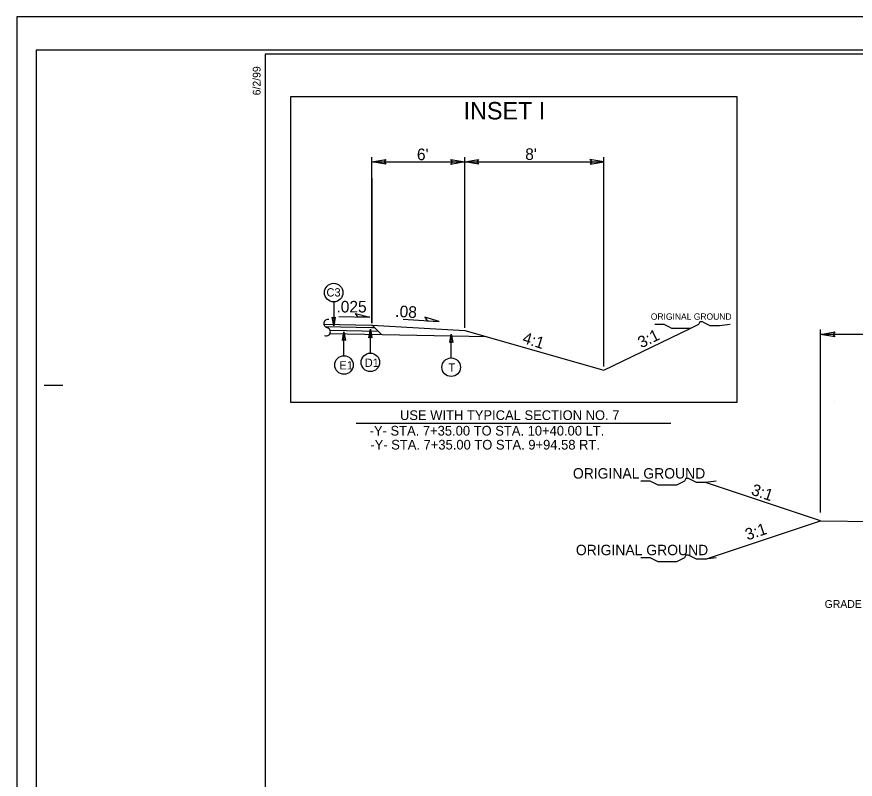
# Model space of a CAD drawing. Extents: x 958711 to 962106, y 831169 to 840840.
# Drawn here: x 958711 to 959274, y 836655 to 837167 of the extents above; entities that cross this region are included whole.
import ezdxf

# ---------------------------------------------------------------- set-up
doc = ezdxf.new("R2010")
doc.units = 0
for name, color, linetype in [('Old_Level_1', 7, 'Continuous'), ('Old_Level_11', 7, 'Continuous'), ('Old_Level_21', 7, 'Continuous'), ('Old_Level_3', 7, 'Continuous'), ('Prop Dimension Text', 7, 'Continuous'), ('Sheet Plot Border Inside CELL', 7, 'Continuous'), ('Sheet Plot Border Outside CELL', 7, 'Continuous'), ('Sheet Typical CELL', 7, 'Continuous'), ('Typical ID Circle CELL', 7, 'Continuous'), ('Typical Terminator CELL', 7, 'Continuous'), ('Typical Text ID Circle CELL', 7, 'Continuous')]:
    doc.layers.add(name, color=color, linetype=linetype)

msp = doc.modelspace()

# ---------------------------------------------------------------- linework, layer by layer
at = {"layer": 'Old_Level_1'}
for p, q in [((958949.49, 836961.06), (958949.49, 837072.49)), ((958949.49, 837069.23), (959011.81, 837069.23)), ((959011.81, 836957.83), (959011.81, 837072.49)), ((959011.81, 837069.23), (959105.29, 837069.23)), ((959105.29, 836931.97), (959105.29, 837072.49)), ((958949.49, 837058.45), (958949.49, 836961)), ((958927.19, 836965.53), (958948.07, 836965.11)), ((958970.53, 836963.64), (958994.65, 836962.16)), ((958917.11, 836960.39), (958949.49, 836959.73)), ((958917.99, 836958.64), (958949.49, 836958.01)), ((958921.3, 836956.32), (958953.71, 836955.66)), ((958949.49, 836959.73), (958949.64, 836959.73)), ((958949.49, 836958.01), (958951.41, 836957.97)), ((958949.64, 836959.73), (958956.01, 836953.36)), ((959105.29, 836929.34), (959163.42, 836957.5)), ((959250.92, 836833.83), (959250.92, 836956.73)), ((958921.29, 836954.06), (959026.37, 836951.94)), ((959317.47, 836953.48), (959250.92, 836953.48)), ((958938.84, 836893.76), (959150.25, 836893.76)), ((959250.92, 836828.25), (959173.74, 836853.98)), ((959173.74, 836802.52), (959250.92, 836828.25)), ((959250.92, 836828.25), (959313.91, 836827.62))]:
    msp.add_line(p, q, dxfattribs=at)
msp.add_lwpolyline([(958894.91, 837113.12), (959194.72, 837113.12), (959194.72, 836907.71), (958894.91, 836907.71)], close=True, dxfattribs=at)
for points in [[(958949.65, 836959.72), (959011.81, 836956.11)], [(959011.81, 836956.11), (959105.29, 836929.34)]]:
    msp.add_lwpolyline(points, dxfattribs=at)
for centre, start, end in [((958919.91, 836960.7), 79.4545, 256.8065), ((958918.72, 836955.2), 248.3355, 78.8593)]:
    msp.add_arc(centre, 2.81, start, end, dxfattribs=at)
at = {"layer": 'Old_Level_11'}
for p, q in [((958940.07, 836965.27), (958938.34, 836967.53)), ((958938.34, 836967.53), (958948.07, 836965.11)), ((958948.07, 836965.11), (958940.07, 836965.27)), ((958985, 836964.98), (958986.65, 836962.65)), ((958994.65, 836962.16), (958985, 836964.98)), ((958986.65, 836962.65), (958994.65, 836962.16))]:
    msp.add_line(p, q, dxfattribs=at)
for points in [[(959260.53, 836951.82), (959250.92, 836953.48), (959260.58, 836955.19), (959259.36, 836953.48)], [(959260.64, 836908.05), (959260.51, 836908.07), (959260.64, 836908.1), (959260.63, 836908.07)]]:
    msp.add_lwpolyline(points, close=True, dxfattribs=at)
at = {"layer": 'Old_Level_21'}
for points in [[(959190.14, 836960.15), (959183.04, 836959.27), (959181.26, 836959.27), (959178.61, 836959.27), (959176.83, 836959.27), (959175.06, 836960.15), (959173.28, 836961.04), (959171.51, 836961.92), (959169.74, 836961.92), (959168.84, 836960.15), (959167.08, 836959.27), (959165.3, 836958.37), (959163.53, 836957.5), (959161.75, 836957.5), (959159.98, 836957.5), (959158.21, 836957.5), (959156.44, 836957.5), (959154.66, 836957.5), (959152.89, 836957.5), (959151.11, 836957.5), (959149.34, 836958.37), (959147.57, 836959.27), (959145.8, 836960.15), (959143.13, 836960.15), (959141.36, 836960.15), (959139.58, 836960.15)], [(959180.83, 836854.86), (959173.74, 836853.98), (959171.96, 836853.98), (959169.3, 836853.98), (959167.52, 836853.98), (959165.75, 836854.86), (959163.98, 836855.76), (959162.21, 836856.64), (959160.43, 836856.64), (959159.53, 836854.86), (959157.77, 836853.98), (959155.99, 836853.08), (959154.22, 836852.21), (959152.45, 836852.21), (959150.68, 836852.21), (959148.9, 836852.21), (959147.13, 836852.21), (959145.35, 836852.21), (959143.58, 836852.21), (959141.81, 836852.21), (959140.04, 836853.08), (959138.27, 836853.98), (959136.5, 836854.86), (959133.82, 836854.86), (959132.05, 836854.86), (959130.28, 836854.86)], [(959180.83, 836803.4), (959173.74, 836802.52), (959171.96, 836802.52), (959169.3, 836802.52), (959167.52, 836802.52), (959165.75, 836803.4), (959163.98, 836804.29), (959162.21, 836805.17), (959160.43, 836805.17), (959159.53, 836803.4), (959157.77, 836802.52), (959155.99, 836801.62), (959154.22, 836800.75), (959152.45, 836800.75), (959150.68, 836800.75), (959148.9, 836800.75), (959147.13, 836800.75), (959145.35, 836800.75), (959143.58, 836800.75), (959141.81, 836800.75), (959140.04, 836801.62), (959138.27, 836802.52), (959136.5, 836803.4), (959133.82, 836803.4), (959132.05, 836803.4), (959130.28, 836803.4)]]:
    msp.add_lwpolyline(points, dxfattribs=at)
at = {"layer": 'Sheet Plot Border Inside CELL'}
msp.add_lwpolyline([(960390.3, 837144.29), (958723.8, 837144.29), (958723.8, 836089.19), (960390.3, 836089.19)], close=True, dxfattribs=at)
at = {"layer": 'Sheet Plot Border Outside CELL'}
msp.add_lwpolyline([(960394.8, 837166.74), (958710.8, 837166.74), (958710.8, 836066.74), (960394.8, 836066.74)], close=True, dxfattribs=at)
at = {"layer": 'Sheet Typical CELL'}
msp.add_line((958729.3, 836919.24), (958741.8, 836919.24), dxfattribs=at)
msp.add_lwpolyline([(960377.8, 837141.74), (958877.8, 837141.74), (958877.8, 836091.74), (960377.8, 836091.74)], close=True, dxfattribs=at)
at = {"layer": 'Typical ID Circle CELL'}
for p, q in [((958923.8, 836975.29), (958923.8, 836959.2)), ((958930.67, 836939.11), (958930.67, 836955.2)), ((958948.43, 836940.87), (958948.43, 836956.96)), ((959002.72, 836937.6), (959002.72, 836953.69))]:
    msp.add_line(p, q, dxfattribs=at)
for centre in [(958923.8, 836981.51), (958930.67, 836932.88), (958948.43, 836934.65), (959002.72, 836931.38)]:
    msp.add_circle(centre, 6.23, dxfattribs=at)
at = {"layer": 'Typical Terminator CELL'}
for points in [[(958958.72, 837067.65), (958949.49, 837069.23), (958958.77, 837070.87), (958957.59, 837069.23)], [(959002.59, 837070.82), (959011.81, 837069.23), (959002.54, 837067.59), (959003.72, 837069.23)], [(959021.04, 837067.65), (959011.81, 837069.23), (959021.09, 837070.87), (959019.91, 837069.23)], [(959096.07, 837067.65), (959105.29, 837069.23), (959096.02, 837070.87), (959097.2, 837069.23)], [(958924.79, 836964.96), (958923.8, 836959.2), (958922.77, 836965), (958923.8, 836964.26)], [(958929.67, 836949.43), (958930.67, 836955.2), (958931.69, 836949.4), (958930.67, 836950.14)], [(958947.44, 836951.2), (958948.43, 836956.96), (958949.46, 836951.16), (958948.43, 836951.9)], [(959001.73, 836947.92), (959002.72, 836953.69), (959003.75, 836947.89), (959002.72, 836948.63)]]:
    msp.add_lwpolyline(points, close=True, dxfattribs=at)

# ---------------------------------------------------------------- texts
at = {"layer": 'Old_Level_1'}
for s, height, p in [('INSET I', 11.716, (959011.11, 837097.79)), ("6'", 7.801, (958979.73, 837070.42)), ('USE WITH TYPICAL SECTION NO. 7', 6.5088, (958968.33, 836895.95)), ('-Y- STA. 7+35.00 TO STA. 10+40.00 LT.', 6.5088, (958947.93, 836885.5)), ('-Y- STA. 7+35.00 TO STA. 9+94.58 RT.', 6.5088, (958948.4, 836876.11)), ('GRADE TO THIS LINE', 5.2473, (959253.71, 836769.76))]:
    msp.add_text(s, height=height, dxfattribs=at).set_placement(p)
for s, rotation, p in [(' .08', 356.4861, (958962.07, 836965.45)), ('3:1', 25.8427, (959130.49, 836944.01)), ('4:1', 342.7093, (959050.06, 836947.84))]:
    msp.add_text(s, height=7.801, rotation=rotation, dxfattribs=at).set_placement(p)
at = {"layer": 'Old_Level_21'}
for height, p in [(4.2722, (959136.88, 836963.26)), (7, (959084.53, 836856.61)), (7, (959086.52, 836805.15))]:
    msp.add_text('ORIGINAL GROUND', height=height, dxfattribs=at).set_placement(p)
at = {"layer": 'Old_Level_3'}
for rotation, p in [(341.5652, (959203.77, 836845.94)), (18.4348, (959201.8, 836815.03))]:
    msp.add_text('3:1', height=7.801, rotation=rotation, dxfattribs=at).set_placement(p)
at = {"layer": 'Prop Dimension Text'}
for s, rotation, p in [("8'", 0, (959052.49, 837070.61)), ('.025', 360, (958925.61, 836968.15))]:
    msp.add_text(s, height=7.801, rotation=rotation, dxfattribs=at).set_placement(p)
at = {"layer": 'Sheet Typical CELL'}
msp.add_text('6/2/99', height=5.25, rotation=90, dxfattribs=at).set_placement((958874.65, 837113.99))
at = {"layer": 'Typical Text ID Circle CELL'}
for s, height, p in [('C3', 5.572, (958918.91, 836978.88)), ('E1', 5.572, (958927.61, 836929.87)), ('D1', 5.572, (958944.62, 836931.63)), ('T', 5.57, (959000.85, 836928.36))]:
    msp.add_text(s, height=height, dxfattribs=at).set_placement(p)

doc.saveas('drawing.dxf')
